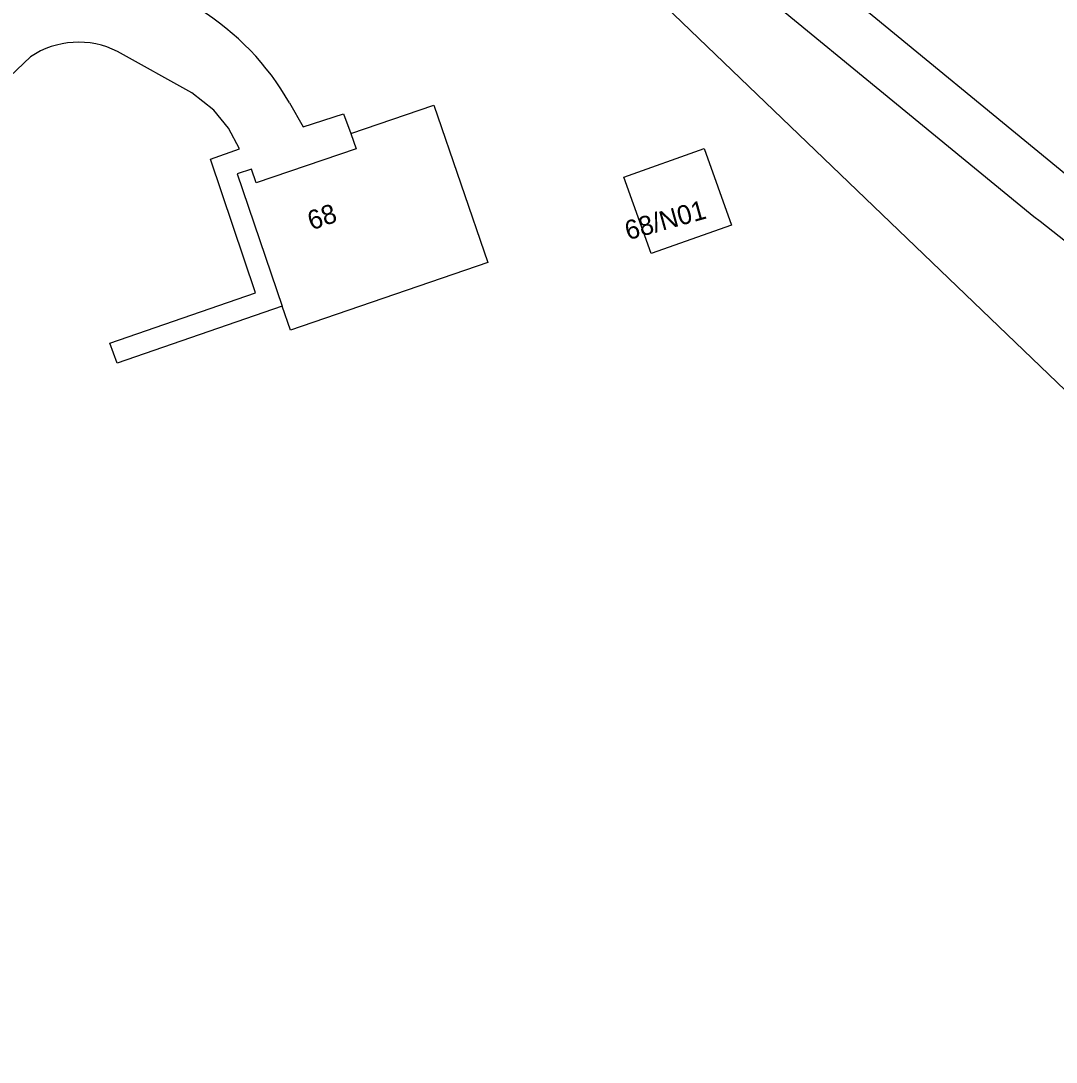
# Model space of a CAD drawing. Extents: x 162417 to 163721, y 384268 to 385416.
# Drawn here: x 163351.6 to 163405.6, y 384814.9 to 384869.2 of the extents above; entities that cross this region are included whole.
import ezdxf

# ---------------------------------------------------------------- set-up
doc = ezdxf.new("R2010")
doc.units = 0
for name, color, linetype in [('IMGEO_Loofbos', 7, 'Continuous'), ('IMGEO_Pand', 7, 'Continuous'), ('IMGEO_Pand_nummerreeks', 7, 'Continuous'), ('IMGEO_Rijbaan_lokaal_open', 7, 'Continuous'), ('IMGEO_Voetpad_open', 7, 'Continuous')]:
    doc.layers.add(name, color=color, linetype=linetype)

msp = doc.modelspace()

# ---------------------------------------------------------------- linework, layer by layer
at = {"layer": 'IMGEO_Loofbos'}
msp.add_lwpolyline([(163449.552, 384814.496), (163444.744, 384812.832), (163371.736, 384882.911)], dxfattribs=at)
at = {"layer": 'IMGEO_Pand'}
for points in [[(163368.799, 384863.337), (163373.132, 384864.82), (163375.942, 384856.61), (163365.646, 384853.085), (163365.216, 384854.34)], [(163368.799, 384863.337), (163369.07, 384862.545), (163363.851, 384860.759), (163363.603, 384861.483), (163362.859, 384861.228), (163365.216, 384854.34)], [(163388.65, 384858.56), (163384.467, 384857.072), (163383.045, 384861.069), (163387.228, 384862.557), (163388.65, 384858.56)]]:
    msp.add_lwpolyline(points, dxfattribs=at)
at = {"layer": 'IMGEO_Rijbaan_lokaal_open'}
for points in [[(163352.08, 384867.341), (163333.129, 384849.312)], [(163365.216, 384854.34), (163356.607, 384851.355), (163356.211, 384852.406), (163363.819, 384855.025), (163361.467, 384861.993), (163362.992, 384862.532), (163362.415, 384863.614), (163361.637, 384864.562), (163360.503, 384865.462), (163356.619, 384867.614)], [(163365.587, 384864.936), (163366.302, 384863.683), (163368.413, 384864.364), (163368.799, 384863.337)]]:
    msp.add_lwpolyline(points, dxfattribs=at)
for centre, radius, start, end in [((163353.586, 384858.101), 13.811, 29.6625, 58.1302), ((163354.583, 384863.601), 4.5, 63.0928, 123.7911)]:
    msp.add_arc(centre, radius, start, end, dxfattribs=at)
at = {"layer": 'IMGEO_Voetpad_open'}
for points in [[(163404.422, 384858.994), (163383.225, 384876.4), (163378.166, 384887.357)], [(163392.196, 384872.647), (163408.421, 384859.297), (163410.514, 384857.379), (163414.147, 384853.364), (163438.619, 384824.336), (163442.822, 384825.228), (163444.598, 384823.469)]]:
    msp.add_lwpolyline(points, dxfattribs=at)
msp.add_arc((163377.171, 384822.171), 45.81, 36.6968, 53.4969, dxfattribs=at)

# ---------------------------------------------------------------- texts
at = {"layer": 'IMGEO_Pand_nummerreeks'}
for s, rotation, p in [('68', 18.8915, (163366.743, 384858.281)), ('68/N01', 15.5241, (163383.252, 384857.768))]:
    msp.add_text(s, height=1, rotation=rotation, dxfattribs=at).set_placement(p)

doc.saveas('drawing.dxf')
